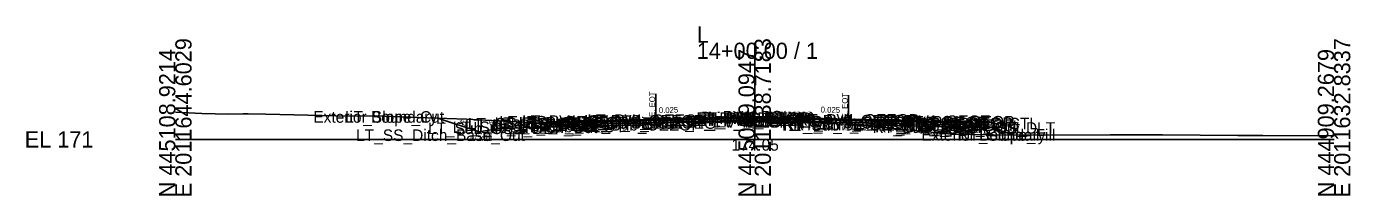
# Model space of a CAD drawing. Extents: x -26 to 4203, y -10 to 9526.
# Drawn here: x -25.7 to 202.8, y 3990.3 to 4019.5 of the extents above; entities that cross this region are included whole.
import ezdxf

# ---------------------------------------------------------------- set-up
doc = ezdxf.new("R2010")
doc.units = 0
for name, color, linetype in [('Default', 7, 'Continuous'), ('Exist CMT Pavement', 7, 'Continuous'), ('Exist Cross Section Cell', 7, 'Continuous'), ('Exist XS Center Line Elevation Label', 7, 'Continuous'), ('Exist XS Ground Line', 7, 'Continuous'), ('Prop CMT Pvmt Course 1', 7, 'Continuous'), ('Prop CMT Pvmt Course 1 Wedge', 7, 'Continuous'), ('Prop CMT Pvmt Course 2', 7, 'Continuous'), ('Prop CMT Pvmt Course 2 Wedge', 7, 'Continuous'), ('Prop CMT Pvmt Course 3', 7, 'Continuous'), ('Prop CMT Pvmt Course 3 Wedge', 7, 'Continuous'), ('Prop CMT Pvmt Surface', 7, 'Continuous'), ('Prop CMT Pvmt Surface Shoulder', 7, 'Continuous'), ('Prop CMT Pvmt Wedge Surface 1', 7, 'Continuous'), ('Prop CMT Pvmt Wedge Surface 2', 7, 'Continuous'), ('Prop CMT Pvmt Wedge Surface 3', 7, 'Continuous'), ('Prop CMT Shld Paved Course 1', 7, 'Continuous'), ('Prop CMT Shld Paved Course 2', 7, 'Continuous'), ('Prop CMT Shld Paved Course 3', 7, 'Continuous'), ('Prop CMT Slope Grass', 7, 'Continuous'), ('Prop CMT Subgrade Earthwork', 7, 'Continuous'), ('Prop XS Ditch Standard Text', 7, 'Continuous'), ('Prop XS Label Text', 7, 'Continuous'), ('Prop XS SE Text', 7, 'Continuous'), ('Prop XS Side Slope Text', 7, 'Continuous'), ('Scratch_Level_0', 7, 'Continuous')]:
    doc.layers.add(name, color=color, linetype=linetype)

msp = doc.modelspace()

# ---------------------------------------------------------------- linework, layer by layer
at = {"layer": 'Exist CMT Pavement'}
for points in [[(81.26, 4002.83), (81.77, 4002.83), (81.83, 4002.83), (82.05, 4002.83), (82.91, 4002.86), (83.92, 4002.87), (84.03, 4002.87), (86.45, 4002.91), (86.48, 4002.91), (86.94, 4002.92), (88.91, 4002.98), (89.03, 4002.98), (91.26, 4003.01), (91.52, 4003.01), (92.18, 4003.02), (94.04, 4003.04), (94.05, 4003.04), (95.44, 4003.05), (96.54, 4003.05), (98.34, 4003.06), (99.04, 4003.06), (99.83, 4003.05), (100, 4003.05)], [(100, 4003.05), (101.55, 4003.03), (103.04, 4003.01), (104.01, 4002.99), (104.45, 4002.99), (105.04, 4002.99), (105.77, 4002.97), (106.55, 4002.96), (107.8, 4002.92), (109.05, 4002.87), (110.14, 4002.84), (111.53, 4002.8), (112.51, 4002.76), (114.06, 4002.7), (115.7, 4002.64), (116.17, 4002.62), (116.23, 4002.61), (117.16, 4002.53), (117.29, 4002.52), (117.45, 4002.51), (117.45, 4002.51)]]:
    msp.add_lwpolyline(points, dxfattribs=at)
at = {"layer": 'Exist Cross Section Cell'}
for p, q in [((100, 4000), (100, 4016.7)), ((0, 4000), (100, 4000)), ((100, 4000), (200, 4000))]:
    msp.add_line(p, q, dxfattribs=at)
at = {"layer": 'Exist XS Ground Line'}
msp.add_lwpolyline([(0, 4004.71), (4.59, 4004.48), (6.9, 4004.41), (9.05, 4004.35), (11.7, 4004.39), (12.58, 4004.41), (15.6, 4004.38), (27.71, 4004.09), (36.22, 4004), (40.23, 4003.86), (46.86, 4003.6), (50.25, 4003.49), (61.17, 4002.9), (67.35, 4002.57), (70.95, 4002.65), (75.95, 4002.74), (81.26, 4002.83), (82.05, 4002.83), (82.91, 4002.86), (84.03, 4002.87), (86.48, 4002.91), (86.94, 4002.92), (89.03, 4002.98), (91.52, 4003.01), (92.18, 4003.02), (94.05, 4003.04), (95.44, 4003.05), (96.54, 4003.05), (98.34, 4003.06), (99.04, 4003.06), (100, 4003.05), (101.55, 4003.03), (103.04, 4003.01), (104.01, 4002.99), (104.45, 4002.99), (105.04, 4002.99), (105.77, 4002.97), (106.55, 4002.96), (107.8, 4002.92), (109.05, 4002.87), (110.14, 4002.84), (111.53, 4002.8), (112.51, 4002.76), (114.06, 4002.7), (115.7, 4002.64), (116.17, 4002.62), (117.45, 4002.51), (119.74, 4002.29), (134, 4000.9), (140.74, 4000.81), (150.44, 4000.71), (161.36, 4000.77), (167.8, 4000.81), (170.36, 4000.77), (183.37, 4000.65), (184.14, 4000.65), (187.7, 4000.67), (200, 4000.64)], dxfattribs=at)
at = {"layer": 'Prop CMT Pvmt Course 1'}
for points in [[(100, 4003.92), (69.12, 4003.14)], [(100, 4003.67), (100, 4003.92)], [(100, 4003.92), (130.76, 4003.15)], [(100, 4003.67), (100, 4003.92)], [(69.12, 4002.89), (81.26, 4003.2)], [(69.12, 4003.14), (69.12, 4002.89)], [(82.91, 4003.36), (100, 4003.79)], [(82.91, 4003.24), (82.91, 4003.36)], [(100, 4003.79), (100, 4003.67), (100, 4003.67)], [(116.17, 4003.39), (100, 4003.79)], [(100, 4003.79), (100, 4003.67), (100, 4003.67)], [(116.17, 4003.26), (116.17, 4003.39)], [(130.76, 4002.9), (117.45, 4003.23)], [(130.76, 4003.15), (130.76, 4002.9)]]:
    msp.add_lwpolyline(points, dxfattribs=at)
at = {"layer": 'Prop CMT Pvmt Course 1 Wedge'}
for points in [[(82.91, 4003.36), (82.91, 4003.36), (83.92, 4003.39), (84.03, 4003.39), (86.45, 4003.45), (86.48, 4003.45), (86.94, 4003.47), (88.91, 4003.51), (89.03, 4003.52), (91.26, 4003.57), (91.52, 4003.58), (92.18, 4003.6), (94.04, 4003.64), (94.05, 4003.64), (95.44, 4003.68), (96.54, 4003.71), (98.34, 4003.75), (99.04, 4003.77), (99.83, 4003.79), (100, 4003.79)], [(100, 4003.67), (99.83, 4003.66), (99.04, 4003.64), (98.34, 4003.63), (96.54, 4003.58), (95.44, 4003.55), (94.05, 4003.52), (94.04, 4003.52), (92.18, 4003.47), (91.52, 4003.45), (91.26, 4003.45), (89.03, 4003.39), (88.91, 4003.39), (86.94, 4003.34), (86.48, 4003.33), (86.45, 4003.33), (84.03, 4003.27), (83.92, 4003.26), (82.91, 4003.24), (82.91, 4003.24)], [(82.91, 4003.24), (82.91, 4003.36)], [(100, 4003.67), (100, 4003.79)], [(100, 4003.79), (100, 4003.67)], [(100, 4003.79), (101.55, 4003.75), (103.04, 4003.72), (104.01, 4003.69), (104.45, 4003.68), (105.04, 4003.67), (105.77, 4003.65), (106.55, 4003.63), (107.8, 4003.6), (109.05, 4003.57), (110.14, 4003.54), (111.53, 4003.5), (112.51, 4003.48), (114.06, 4003.44), (115.7, 4003.4), (116.17, 4003.39)], [(116.17, 4003.26), (115.7, 4003.27), (114.06, 4003.32), (112.51, 4003.35), (111.53, 4003.38), (110.14, 4003.41), (109.05, 4003.44), (107.8, 4003.47), (106.55, 4003.5), (105.77, 4003.52), (105.04, 4003.54), (104.45, 4003.56), (104.01, 4003.57), (103.04, 4003.59), (101.55, 4003.63), (100, 4003.67)], [(116.17, 4003.39), (116.17, 4003.26)]]:
    msp.add_lwpolyline(points, dxfattribs=at)
at = {"layer": 'Prop CMT Pvmt Course 2'}
for points in [[(82.91, 4003.24), (69.12, 4002.89)], [(69.12, 4002.89), (69.12, 4002.56)], [(69.12, 4002.56), (81.26, 4002.86)], [(82.91, 4002.91), (82.91, 4003.24)], [(116.17, 4002.93), (116.17, 4003.26)], [(116.17, 4003.26), (130.76, 4002.9)], [(130.76, 4002.56), (117.45, 4002.9)], [(130.76, 4002.9), (130.76, 4002.56)]]:
    msp.add_lwpolyline(points, dxfattribs=at)
at = {"layer": 'Prop CMT Pvmt Course 2 Wedge'}
for points in [[(82.91, 4003.24), (82.91, 4003.24), (83.92, 4003.26), (84.03, 4003.27), (86.45, 4003.33), (86.48, 4003.33), (86.94, 4003.34), (88.91, 4003.39), (89.03, 4003.39), (91.26, 4003.45), (91.52, 4003.45), (92.18, 4003.47), (94.04, 4003.52), (94.05, 4003.52), (95.44, 4003.55), (96.54, 4003.58), (98.34, 4003.63), (99.04, 4003.64), (99.83, 4003.66), (100, 4003.67)], [(100, 4003.33), (99.83, 4003.33), (99.04, 4003.31), (98.34, 4003.29), (96.54, 4003.25), (95.44, 4003.22), (94.05, 4003.18), (94.04, 4003.18), (92.18, 4003.14), (91.52, 4003.12), (91.26, 4003.12), (89.03, 4003.06), (88.91, 4003.06), (86.94, 4003.01), (86.48, 4003), (86.45, 4002.99), (84.03, 4002.93), (83.92, 4002.93), (82.91, 4002.91), (82.91, 4002.91)], [(82.91, 4002.91), (82.91, 4003.24)], [(100, 4003.33), (100, 4003.67)], [(100, 4003.67), (100, 4003.33)], [(100, 4003.67), (101.55, 4003.63), (103.04, 4003.59), (104.01, 4003.57), (104.45, 4003.56), (105.04, 4003.54), (105.77, 4003.52), (106.55, 4003.5), (107.8, 4003.47), (109.05, 4003.44), (110.14, 4003.41), (111.53, 4003.38), (112.51, 4003.35), (114.06, 4003.32), (115.7, 4003.27), (116.17, 4003.26)], [(116.17, 4002.93), (115.7, 4002.94), (114.06, 4002.98), (112.51, 4003.02), (111.53, 4003.05), (110.14, 4003.08), (109.05, 4003.11), (107.8, 4003.14), (106.55, 4003.17), (105.77, 4003.19), (105.04, 4003.21), (104.45, 4003.22), (104.01, 4003.23), (103.04, 4003.26), (101.55, 4003.29), (100, 4003.33)], [(116.17, 4003.26), (116.17, 4002.93)]]:
    msp.add_lwpolyline(points, dxfattribs=at)
at = {"layer": 'Prop CMT Pvmt Course 3'}
for points in [[(82.91, 4002.91), (69.12, 4002.56)], [(69.12, 4002.23), (82.91, 4002.57)], [(69.12, 4002.56), (69.12, 4002.23)], [(82.91, 4002.57), (82.91, 4002.91)], [(116.17, 4002.93), (130.76, 4002.56)], [(116.17, 4002.6), (116.17, 4002.93)], [(130.76, 4002.23), (116.17, 4002.6)], [(130.76, 4002.56), (130.76, 4002.23)]]:
    msp.add_lwpolyline(points, dxfattribs=at)
at = {"layer": 'Prop CMT Pvmt Course 3 Wedge'}
for points in [[(100, 4003.05), (99.83, 4003.05), (99.04, 4003.06), (98.34, 4003.06), (96.54, 4003.05), (95.44, 4003.05), (94.05, 4003.04), (94.04, 4003.04), (92.18, 4003.02), (91.52, 4003.01), (91.26, 4003.01), (89.03, 4002.98), (88.91, 4002.98), (86.94, 4002.92), (86.48, 4002.91), (86.45, 4002.91), (84.03, 4002.87), (83.92, 4002.87), (82.91, 4002.86), (82.05, 4002.83), (81.83, 4002.83), (81.77, 4002.83), (81.26, 4002.83)], [(82.91, 4002.91), (82.91, 4002.91), (83.92, 4002.93), (84.03, 4002.93), (86.45, 4002.99), (86.48, 4003), (86.94, 4003.01), (88.91, 4003.06), (89.03, 4003.06), (91.26, 4003.11), (91.52, 4003.12), (92.18, 4003.14), (94.04, 4003.18), (94.05, 4003.18), (95.44, 4003.22), (96.54, 4003.25), (98.34, 4003.29), (99.04, 4003.31), (99.83, 4003.33), (100, 4003.33)], [(82.91, 4002.87), (82.91, 4002.91)], [(100, 4003.05), (100, 4003.33)], [(100, 4003.33), (100, 4003.05)], [(100, 4003.33), (101.55, 4003.29), (103.04, 4003.26), (104.01, 4003.23), (104.45, 4003.22), (105.04, 4003.21), (105.77, 4003.19), (106.55, 4003.17), (107.8, 4003.14), (109.05, 4003.11), (110.14, 4003.08), (111.53, 4003.05), (112.51, 4003.02), (114.06, 4002.98), (115.7, 4002.94), (116.17, 4002.93)], [(117.45, 4002.51), (117.45, 4002.51), (117.29, 4002.52), (117.16, 4002.53), (116.23, 4002.61), (116.17, 4002.62), (115.7, 4002.64), (114.06, 4002.7), (112.51, 4002.76), (111.53, 4002.8), (110.14, 4002.84), (109.05, 4002.87), (107.8, 4002.92), (106.55, 4002.96), (105.77, 4002.97), (105.04, 4002.99), (104.45, 4002.99), (104.01, 4002.99), (103.04, 4003.01), (101.55, 4003.03), (100, 4003.05)], [(116.17, 4002.93), (116.17, 4002.6)]]:
    msp.add_lwpolyline(points, dxfattribs=at)
at = {"layer": 'Prop CMT Pvmt Surface'}
for points in [[(100, 4003.92), (69.12, 4003.14)], [(100, 4003.92), (130.76, 4003.15)]]:
    msp.add_lwpolyline(points, dxfattribs=at)
at = {"layer": 'Prop CMT Pvmt Surface Shoulder'}
for points in [[(69.12, 4003.14), (65.12, 4003.05)], [(130.76, 4003.15), (134.76, 4003.05)]]:
    msp.add_lwpolyline(points, dxfattribs=at)
at = {"layer": 'Prop CMT Pvmt Wedge Surface 1'}
for points in [[(81.26, 4003.2), (69.12, 4002.89)], [(69.12, 4002.89), (69.12, 4003.14)], [(100, 4003.79), (82.91, 4003.36)], [(82.91, 4003.36), (82.91, 4003.24)], [(100, 4003.79), (116.17, 4003.39)], [(116.17, 4003.39), (116.17, 4003.26)], [(117.45, 4003.23), (130.76, 4002.9)], [(130.76, 4002.9), (130.76, 4003.15)]]:
    msp.add_lwpolyline(points, dxfattribs=at)
at = {"layer": 'Prop CMT Pvmt Wedge Surface 2'}
for points in [[(69.12, 4002.89), (69.12, 4003.14)], [(100, 4003.67), (82.91, 4003.24)], [(100, 4003.67), (116.17, 4003.26)], [(130.76, 4002.9), (130.76, 4003.15)]]:
    msp.add_lwpolyline(points, dxfattribs=at)
at = {"layer": 'Prop CMT Pvmt Wedge Surface 3'}
for points in [[(69.12, 4002.56), (69.12, 4003.14)], [(100, 4003.33), (82.91, 4002.91)], [(100, 4003.33), (116.17, 4002.93)], [(130.76, 4002.56), (130.76, 4003.15)]]:
    msp.add_lwpolyline(points, dxfattribs=at)
at = {"layer": 'Prop CMT Shld Paved Course 1'}
for points in [[(69.12, 4003.14), (65.12, 4003.05), (64.86, 4002.79)], [(64.86, 4002.79), (69.12, 4002.89)], [(69.12, 4002.89), (69.12, 4003.14)], [(130.76, 4003.15), (134.76, 4003.05), (135.02, 4002.79)], [(130.76, 4002.9), (130.76, 4003.15)], [(135.02, 4002.79), (130.76, 4002.9)]]:
    msp.add_lwpolyline(points, dxfattribs=at)
at = {"layer": 'Prop CMT Shld Paved Course 2'}
for points in [[(69.12, 4002.89), (64.86, 4002.79), (64.52, 4002.45)], [(64.52, 4002.45), (69.12, 4002.56)], [(69.12, 4002.56), (69.12, 4002.89)], [(130.76, 4002.9), (135.02, 4002.79), (135.36, 4002.45)], [(130.76, 4002.56), (130.76, 4002.9)], [(135.36, 4002.45), (130.76, 4002.56)]]:
    msp.add_lwpolyline(points, dxfattribs=at)
at = {"layer": 'Prop CMT Shld Paved Course 3'}
for points in [[(69.12, 4002.56), (65.02, 4002.46), (64.52, 4002.45), (64.18, 4002.1)], [(64.18, 4002.1), (69.12, 4002.23)], [(69.12, 4002.23), (69.12, 4002.56)], [(130.76, 4002.56), (134.86, 4002.46), (135.36, 4002.45), (135.71, 4002.11)], [(130.76, 4002.23), (130.76, 4002.56)], [(135.71, 4002.11), (130.76, 4002.23)]]:
    msp.add_lwpolyline(points, dxfattribs=at)
at = {"layer": 'Prop CMT Slope Grass'}
for points in [[(65.12, 4003.05), (61.12, 4002.72), (52.45, 4001.28), (45.31, 4003.66)], [(134.76, 4003.05), (138.76, 4002.73), (144.63, 4000.77)]]:
    msp.add_lwpolyline(points, dxfattribs=at)
at = {"layer": 'Prop CMT Subgrade Earthwork'}
for points in [[(63.68, 4002.09), (56.2, 4001.91)], [(69.12, 4002.23), (63.68, 4002.09)], [(82.91, 4002.57), (69.12, 4002.23)], [(82.91, 4002.57), (82.91, 4002.86)], [(116.17, 4002.62), (116.17, 4002.6)], [(116.17, 4002.6), (130.76, 4002.23)], [(130.76, 4002.23), (136.21, 4002.1)], [(136.21, 4002.1), (141.02, 4001.97)]]:
    msp.add_lwpolyline(points, dxfattribs=at)
at = {"layer": 'Prop XS Label Text'}
for p, q in [((82.91, 4007.86), (82.91, 4002.86)), ((116.17, 4007.62), (116.17, 4002.62))]:
    msp.add_line(p, q, dxfattribs=at)

# ---------------------------------------------------------------- texts
at = {"layer": 'Default'}
msp.add_text('-', height=0.0001, dxfattribs=at).set_placement((0, 4000))
at = {"layer": 'Exist Cross Section Cell'}
for s, p in [('L', (90, 4016.7)), ('14+00.00 / 1', (90, 4013.9)), ('EL 171', (-26, 3998.6))]:
    msp.add_text(s, height=2.8, dxfattribs=at).set_placement(p)
for s, p in [('N 445108.9214', (0, 3990)), ('E 2011644.6029', (2.8, 3990)), ('N 445009.0947', (100, 3990)), ('E 2011638.7183', (102.8, 3990)), ('N 444909.2679', (200, 3990)), ('E 2011632.8337', (202.8, 3990))]:
    msp.add_text(s, height=2.8, rotation=90, dxfattribs=at).set_placement(p)
at = {"layer": 'Exist XS Center Line Elevation Label'}
msp.add_text('174.05', height=2, dxfattribs=at).set_placement((95.98, 3998.05))
at = {"layer": 'Prop XS Ditch Standard Text'}
msp.add_text('172.28', height=1, dxfattribs=at).set_placement((50.63, 3999.71))
at = {"layer": 'Prop XS Label Text'}
for p in [(82.81, 4003.88), (116.07, 4003.64)]:
    msp.add_text('E. EOT', height=1, rotation=90, dxfattribs=at).set_placement(p)
at = {"layer": 'Prop XS SE Text'}
for rotation, p in [(1.4322, (83.46, 4004.53)), (358.568, (111.38, 4004.65))]:
    msp.add_text('0.025', height=1, rotation=rotation, dxfattribs=at).set_placement(p)
at = {"layer": 'Prop XS Side Slope Text'}
for s, rotation, p in [('3:1', 341.5676, (48.66, 4002.8)), ('6:1', 9.4617, (54.22, 4002.33)), ('3:1', 341.5683, (141.18, 4002.71))]:
    msp.add_text(s, height=1, rotation=rotation, dxfattribs=at).set_placement(p)
at = {"layer": 'Scratch_Level_0'}
for s, p in [('Exterior Boundary', (23.81, 4002.88)), ('LT_Slope_Cut', (29.3, 4002.88)), ('LT_PS1_OEOP', (55.92, 4002.05)), ('LT_PV2_OEOT', (59.29, 4001.89)), ('LT_PV1_OEOT', (59.86, 4002.14)), ('LT_Sub Tie Out', (68.6, 4001.83)), ('LT_PV2_OEEOP', (70.57, 4002.2)), ('LT_PV3_OEEOP', (70.57, 4001.86)), ('LT_PV1_OEEOP', (71.14, 4002.32)), ('RT_PV_IEEOP_EG', (88.14, 4002.05)), ('LT_PV_IEEOP_EG', (88.19, 4002.05)), ('RT_PV2_IEEOP', (89.91, 4002.67)), ('RT_PV3_IEEOP', (89.91, 4002.33)), ('LT_PV2_IEEOP', (89.95, 4002.67)), ('LT_PV3_IEEOP', (89.95, 4002.33)), ('RT_PV1_IEEOP', (90.47, 4002.79)), ('LT_PV1_IEEOP', (90.52, 4002.79)), ('PV2_PGL', (93.91, 4002.67)), ('PV1_PGL', (94.47, 4002.92)), ('RT_PV2_OEEOP', (106.71, 4002.23)), ('RT_PV3_OEEOP', (106.71, 4001.9)), ('RT_PV1_OEEOP', (107.28, 4002.36)), ('RT_PV2_OEOT', (120.89, 4001.9)), ('RT_PV1_OEOT', (121.45, 4002.15)), ('RT_PS1_OEOP', (125.52, 4002.05)), ('LT_SS_Ditch_Base_Out', (31.2, 3999.72)), ('LT_Sub_OSS_DLT', (43.6, 4000.91)), ('LT_Sub_Trench_Out', (47.88, 4001.09)), ('LT_PS3_Shelf_Out', (50, 4001.43)), ('LT_GS_OS_CTL', (50.49, 4001.72)), ('LT_PS3_OEOP', (54.76, 4001.45)), ('LT_PS2_OEOP', (55.1, 4001.79)), ('LT_Sub_OEOT', (59.2, 4001.23)), ('LT_PV3_OEOT', (59.29, 4001.56)), ('LT_PV_OEEOP_EG', (68.81, 4001.83)), ('LT_Sub_OEEOP', (70.47, 4001.53)), ('RT_Sub Tie Out', (104.74, 4001.51)), ('RT_PV_OEEOP_EG', (104.95, 4001.51)), ('RT_Sub_OEEOP', (106.62, 4001.56)), ('RT_Sub_Trench_Out', (120.36, 4001.1)), ('RT_Sub_OEOT', (120.79, 4001.23)), ('RT_PV3_OEOT', (120.89, 4001.56)), ('RT_PS3_Shelf_Out', (121.8, 4001.44)), ('RT_PS2_OEOP', (125.21, 4001.79)), ('RT_PS3_OEOP', (125.55, 4001.45)), ('RT_GS_OS_CTL', (128.08, 4001.73)), ('RT_Sub_OSS_DLT', (128.38, 4000.97)), ('Exterior Boundary', (128.78, 3999.77)), ('RT_Slope_Fill', (135.11, 3999.77))]:
    msp.add_text(s, height=2, dxfattribs=at).set_placement(p)

doc.saveas('drawing.dxf')
